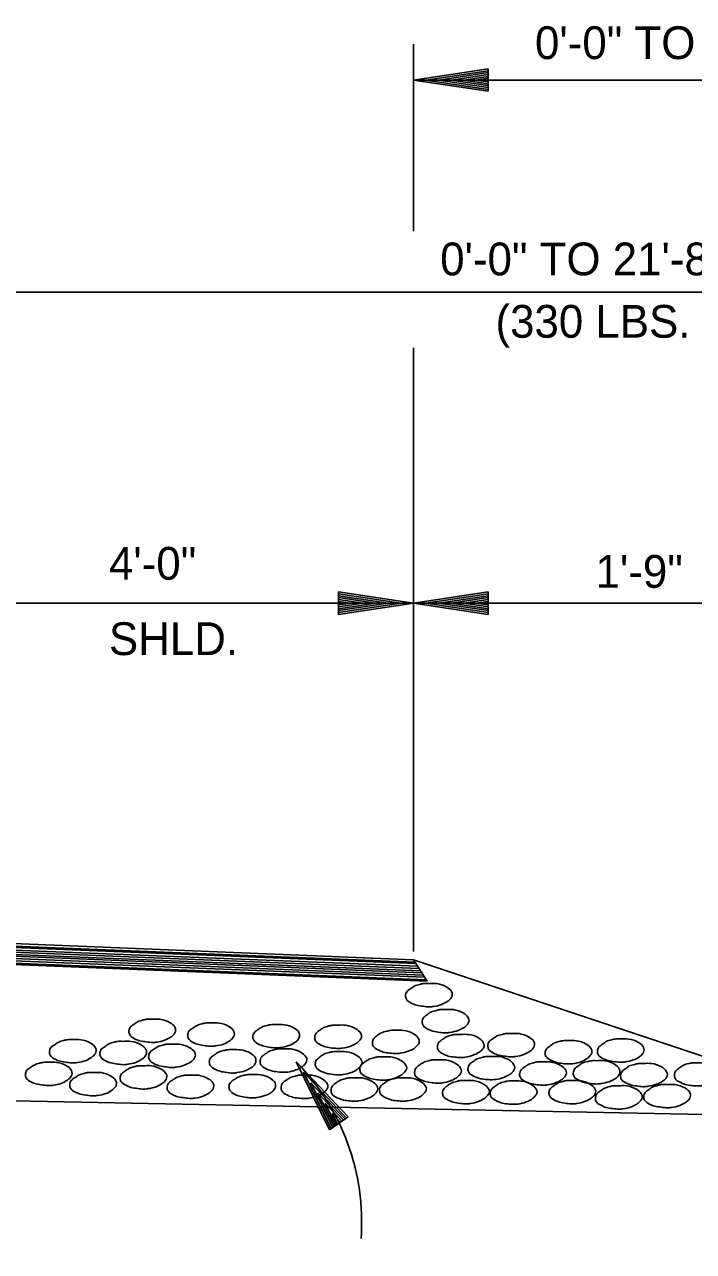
# Model space of a CAD drawing. Extents: x 836 to 5683, y -463 to 1545.
# Drawn here: x 4647.3 to 4769.7, y -331.6 to -107 of the extents above; entities that cross this region are included whole.
import ezdxf

# ---------------------------------------------------------------- set-up
doc = ezdxf.new("R2010")
doc.units = 0
doc.layers.add('Default', color=7, linetype='Continuous')

msp = doc.modelspace()

# ---------------------------------------------------------------- linework, layer by layer
at = {"layer": 'Default'}
for p, q in [((4718.46, -110.62), (4718.46, -144.83)), ((4732.16, -115.15), (4718.46, -117.19)), ((4732.16, -115.48), (4720.73, -117.19)), ((4732.16, -115.83), (4723.1, -117.19)), ((4732.16, -116.16), (4725.38, -117.19)), ((4732.16, -116.55), (4727.7, -117.19)), ((4732.16, -115.15), (4732.16, -119.25)), ((4732.16, -119.25), (4718.46, -117.19)), ((4953.92, -117.19), (4718.46, -117.19)), ((4732.16, -118.9), (4720.73, -117.19)), ((4732.16, -118.56), (4723.1, -117.19)), ((4732.16, -118.2), (4725.38, -117.19)), ((4732.16, -117.87), (4727.7, -117.19)), ((4732.16, -116.86), (4729.97, -117.19)), ((4732.16, -117.52), (4729.97, -117.19)), ((4954.76, -155.99), (4633.46, -155.99)), ((4718.46, -166.17), (4718.46, -189.97)), ((4718.46, -189.97), (4718.46, -276.66)), ((4704.78, -210.88), (4718.46, -212.92)), ((4704.78, -210.88), (4704.78, -214.98)), ((4732.16, -210.88), (4718.46, -212.92)), ((4732.16, -214.98), (4732.16, -210.88)), ((4629.11, -212.92), (4718.46, -212.92)), ((4704.78, -211.21), (4716.17, -212.92)), ((4704.78, -211.57), (4713.83, -212.92)), ((4704.78, -211.9), (4711.56, -212.92)), ((4704.78, -212.27), (4709.2, -212.92)), ((4704.78, -212.6), (4706.93, -212.92)), ((4704.78, -214.98), (4718.46, -212.92)), ((4704.78, -213.61), (4709.2, -212.92)), ((4704.78, -214.3), (4713.83, -212.92)), ((4704.78, -214.64), (4716.17, -212.92)), ((4704.78, -213.94), (4711.56, -212.92)), ((4704.78, -213.25), (4706.93, -212.92)), ((4718.46, -212.92), (4805.51, -212.92)), ((4732.16, -214.98), (4718.46, -212.92)), ((4732.16, -211.21), (4720.74, -212.92)), ((4732.16, -214.64), (4720.74, -212.92)), ((4732.16, -211.57), (4723.09, -212.92)), ((4732.16, -214.3), (4723.09, -212.92)), ((4732.16, -211.9), (4725.38, -212.92)), ((4732.16, -213.94), (4725.38, -212.92)), ((4732.16, -212.27), (4727.69, -212.92)), ((4732.16, -213.61), (4727.69, -212.92)), ((4732.16, -212.6), (4729.96, -212.92)), ((4732.16, -213.25), (4729.96, -212.92)), ((4450.52, -267.41), (4718.46, -278.19)), ((4450.81, -267.86), (4718.74, -278.64)), ((4451.02, -268.2), (4718.91, -278.91)), ((4451.3, -268.63), (4719.21, -279.38)), ((4451.57, -269.06), (4719.46, -279.77)), ((4451.81, -269.43), (4719.76, -280.24)), ((4452.05, -269.82), (4719.96, -280.56)), ((4452.3, -270.21), (4720.25, -281.02)), ((4452.57, -270.64), (4720.5, -281.4)), ((4452.82, -271.03), (4720.79, -281.87)), ((4453.03, -271.36), (4720.95, -282.13)), ((4718.46, -278.19), (4915.99, -344.03)), ((4718.46, -278.19), (4720.96, -282.13)), ((4703.13, -309.3), (4697.01, -296.88)), ((4706.51, -306.93), (4697.01, -296.88)), ((4471.56, -300.53), (4805.51, -307.21)), ((4703.41, -309.12), (4698.33, -298.75)), ((4706.23, -307.17), (4698.33, -298.75)), ((4705.94, -307.34), (4699.67, -300.7)), ((4703.71, -308.91), (4699.67, -300.7)), ((4704, -308.71), (4700.96, -302.57)), ((4705.65, -307.56), (4700.96, -302.57)), ((4705.37, -307.74), (4702.3, -304.47)), ((4704.28, -308.49), (4702.3, -304.47)), ((4703.13, -309.3), (4706.51, -306.93)), ((4705.08, -307.95), (4703.6, -306.33)), ((4704.56, -308.32), (4703.6, -306.33))]:
    msp.add_line(p, q, dxfattribs=at)
msp.add_arc((4667.16, -326.19), 41.83, 355.8236, 44.4822, dxfattribs=at)
for points in [[(4721.22, -282.55), (4722.75, -282.56), (4724.57, -283.2), (4725.46, -284.03), (4725.58, -284.57), (4725.12, -285.49), (4724.6, -285.88), (4723.6, -286.4), (4722.14, -286.74), (4721.38, -286.82), (4720.27, -286.71), (4719.01, -286.5), (4718.06, -286.13), (4717.18, -285.4), (4717.03, -284.82), (4717.29, -284), (4717.99, -283.47), (4718.63, -283.05), (4719.65, -282.7), (4720.28, -282.56), (4721.22, -282.55)], [(4724.26, -287.3), (4725.77, -287.32), (4727.58, -287.94), (4728.48, -288.81), (4728.64, -289.31), (4728.16, -290.25), (4727.63, -290.67), (4726.64, -291.12), (4725.16, -291.51), (4724.4, -291.57), (4723.28, -291.49), (4722.05, -291.27), (4721.1, -290.89), (4720.22, -290.18), (4720.07, -289.58), (4720.33, -288.78), (4721.02, -288.2), (4721.66, -287.77), (4722.69, -287.46), (4723.31, -287.32), (4724.26, -287.3)], [(4670.59, -289.07), (4672.12, -289.08), (4673.94, -289.72), (4674.83, -290.55), (4674.95, -291.09), (4674.49, -292.01), (4673.97, -292.4), (4672.97, -292.92), (4671.51, -293.26), (4670.75, -293.34), (4669.64, -293.23), (4668.38, -293.02), (4667.43, -292.65), (4666.55, -291.92), (4666.4, -291.34), (4666.66, -290.52), (4667.36, -289.99), (4668, -289.57), (4669.02, -289.22), (4669.65, -289.08), (4670.59, -289.07)], [(4681.35, -289.77), (4682.88, -289.78), (4684.7, -290.42), (4685.59, -291.25), (4685.71, -291.79), (4685.25, -292.71), (4684.73, -293.1), (4683.73, -293.62), (4682.27, -293.96), (4681.51, -294.04), (4680.4, -293.93), (4679.14, -293.72), (4678.19, -293.35), (4677.31, -292.62), (4677.16, -292.04), (4677.42, -291.22), (4678.12, -290.69), (4678.76, -290.27), (4679.78, -289.92), (4680.41, -289.78), (4681.35, -289.77)], [(4693.27, -290.04), (4694.81, -290.08), (4696.64, -290.69), (4697.53, -291.56), (4697.63, -292.06), (4697.17, -293.01), (4696.65, -293.42), (4695.67, -293.9), (4694.19, -294.26), (4693.43, -294.32), (4692.32, -294.23), (4691.1, -294.01), (4690.14, -293.64), (4689.25, -292.93), (4689.09, -292.33), (4689.36, -291.5), (4690.05, -290.97), (4690.7, -290.53), (4691.7, -290.21), (4692.34, -290.08), (4693.27, -290.04)], [(4704.59, -290.16), (4706.1, -290.18), (4707.92, -290.82), (4708.84, -291.67), (4708.98, -292.17), (4708.48, -293.11), (4707.95, -293.53), (4706.99, -294.01), (4705.48, -294.38), (4704.74, -294.43), (4703.61, -294.35), (4702.39, -294.14), (4701.44, -293.75), (4700.55, -293.04), (4700.41, -292.42), (4700.68, -291.64), (4701.36, -291.08), (4702.02, -290.64), (4703, -290.32), (4703.62, -290.18), (4704.59, -290.16)], [(4715.18, -291.11), (4716.66, -291.13), (4718.5, -291.75), (4719.39, -292.63), (4719.54, -293.14), (4719.04, -294.04), (4718.51, -294.48), (4717.53, -294.93), (4716.04, -295.32), (4715.29, -295.37), (4714.17, -295.29), (4712.95, -295.09), (4712, -294.7), (4711.1, -294), (4710.96, -293.39), (4711.24, -292.59), (4711.91, -292.02), (4712.56, -291.58), (4713.57, -291.29), (4714.18, -291.13), (4715.18, -291.11)], [(4727.06, -291.86), (4728.54, -291.88), (4730.38, -292.47), (4731.25, -293.34), (4731.41, -293.84), (4730.94, -294.79), (4730.4, -295.19), (4729.41, -295.66), (4727.95, -296.04), (4727.17, -296.1), (4726.06, -296.02), (4724.83, -295.82), (4723.88, -295.41), (4722.98, -294.7), (4722.85, -294.13), (4723.12, -293.31), (4723.8, -292.76), (4724.43, -292.33), (4725.46, -291.98), (4726.08, -291.88), (4727.06, -291.86)], [(4736.27, -291.7), (4737.8, -291.71), (4739.62, -292.35), (4740.51, -293.18), (4740.63, -293.72), (4740.17, -294.64), (4739.65, -295.03), (4738.65, -295.55), (4737.19, -295.89), (4736.43, -295.97), (4735.32, -295.86), (4734.06, -295.65), (4733.11, -295.28), (4732.23, -294.55), (4732.08, -293.97), (4732.34, -293.15), (4733.04, -292.62), (4733.68, -292.2), (4734.7, -291.85), (4735.33, -291.71), (4736.27, -291.7)], [(4656.05, -292.82), (4657.58, -292.83), (4659.4, -293.47), (4660.29, -294.3), (4660.41, -294.84), (4659.95, -295.76), (4659.43, -296.15), (4658.43, -296.67), (4656.97, -297.01), (4656.21, -297.09), (4655.1, -296.98), (4653.84, -296.77), (4652.89, -296.4), (4652.01, -295.67), (4651.86, -295.09), (4652.12, -294.27), (4652.82, -293.74), (4653.46, -293.32), (4654.48, -292.97), (4655.11, -292.83), (4656.05, -292.82)], [(4665.28, -293.13), (4666.81, -293.14), (4668.63, -293.78), (4669.52, -294.61), (4669.64, -295.15), (4669.18, -296.07), (4668.66, -296.46), (4667.66, -296.98), (4666.2, -297.32), (4665.44, -297.4), (4664.33, -297.29), (4663.07, -297.08), (4662.12, -296.71), (4661.24, -295.98), (4661.09, -295.4), (4661.35, -294.58), (4662.05, -294.05), (4662.69, -293.63), (4663.71, -293.28), (4664.34, -293.14), (4665.28, -293.13)], [(4674.2, -293.65), (4675.73, -293.66), (4677.55, -294.3), (4678.44, -295.13), (4678.56, -295.67), (4678.1, -296.59), (4677.58, -296.98), (4676.58, -297.5), (4675.12, -297.84), (4674.36, -297.92), (4673.25, -297.81), (4671.99, -297.6), (4671.04, -297.23), (4670.16, -296.5), (4670.01, -295.92), (4670.27, -295.1), (4670.97, -294.57), (4671.61, -294.15), (4672.63, -293.8), (4673.26, -293.66), (4674.2, -293.65)], [(4746.75, -293), (4748.26, -293.01), (4750.08, -293.65), (4751, -294.51), (4751.14, -295.01), (4750.64, -295.94), (4750.12, -296.36), (4749.15, -296.85), (4747.64, -297.22), (4746.9, -297.27), (4745.77, -297.19), (4744.55, -296.97), (4743.6, -296.58), (4742.71, -295.88), (4742.57, -295.26), (4742.84, -294.48), (4743.52, -293.92), (4744.18, -293.48), (4745.16, -293.15), (4745.78, -293.01), (4746.75, -293)], [(4756.33, -292.69), (4757.84, -292.71), (4759.68, -293.33), (4760.55, -294.19), (4760.69, -294.69), (4760.21, -295.64), (4759.7, -296.04), (4758.7, -296.53), (4757.23, -296.9), (4756.47, -296.95), (4755.36, -296.87), (4754.12, -296.65), (4753.15, -296.26), (4752.26, -295.56), (4752.14, -294.98), (4752.42, -294.16), (4753.11, -293.61), (4753.73, -293.18), (4754.74, -292.83), (4755.38, -292.71), (4756.33, -292.69)], [(4685.29, -294.64), (4686.83, -294.69), (4688.65, -295.3), (4689.54, -296.17), (4689.65, -296.67), (4689.18, -297.62), (4688.67, -298.02), (4687.69, -298.51), (4686.21, -298.86), (4685.44, -298.93), (4684.34, -298.83), (4683.12, -298.61), (4682.15, -298.24), (4681.27, -297.54), (4681.11, -296.93), (4681.38, -296.11), (4682.06, -295.58), (4682.72, -295.14), (4683.71, -294.81), (4684.35, -294.69), (4685.29, -294.64)], [(4694.57, -294.52), (4696.09, -294.53), (4697.91, -295.17), (4698.83, -296.03), (4698.97, -296.53), (4698.47, -297.46), (4697.94, -297.88), (4696.97, -298.37), (4695.46, -298.74), (4694.73, -298.79), (4693.59, -298.71), (4692.38, -298.49), (4691.43, -298.1), (4690.54, -297.4), (4690.4, -296.78), (4690.66, -296), (4691.35, -295.44), (4692, -295), (4692.98, -294.67), (4693.61, -294.53), (4694.57, -294.52)], [(4704.67, -295), (4706.18, -295.02), (4708.01, -295.65), (4708.93, -296.51), (4709.07, -297.01), (4708.57, -297.94), (4708.04, -298.37), (4707.07, -298.85), (4705.56, -299.22), (4704.83, -299.27), (4703.69, -299.19), (4702.48, -298.97), (4701.52, -298.58), (4700.64, -297.88), (4700.5, -297.26), (4700.76, -296.48), (4701.45, -295.92), (4702.1, -295.48), (4703.08, -295.16), (4703.71, -295.02), (4704.67, -295)], [(4712.84, -295.97), (4714.35, -295.98), (4716.17, -296.62), (4717.09, -297.48), (4717.23, -297.98), (4716.73, -298.91), (4716.2, -299.33), (4715.24, -299.81), (4713.73, -300.19), (4712.99, -300.24), (4711.86, -300.16), (4710.64, -299.94), (4709.69, -299.55), (4708.8, -298.85), (4708.66, -298.23), (4708.93, -297.45), (4709.61, -296.89), (4710.27, -296.45), (4711.25, -296.12), (4711.87, -295.98), (4712.84, -295.97)], [(4732.65, -295.9), (4734.13, -295.91), (4735.97, -296.54), (4736.84, -297.41), (4737, -297.91), (4736.53, -298.84), (4735.99, -299.25), (4735, -299.73), (4733.54, -300.11), (4732.76, -300.15), (4731.67, -300.09), (4730.42, -299.89), (4729.47, -299.48), (4728.58, -298.78), (4728.44, -298.19), (4728.72, -297.36), (4729.41, -296.8), (4730.02, -296.37), (4731.05, -296.07), (4731.69, -295.91), (4732.65, -295.9)], [(4651.64, -296.97), (4653.17, -296.98), (4654.99, -297.62), (4655.88, -298.45), (4656, -298.99), (4655.54, -299.91), (4655.02, -300.3), (4654.02, -300.82), (4652.56, -301.16), (4651.8, -301.24), (4650.69, -301.13), (4649.43, -300.92), (4648.48, -300.55), (4647.6, -299.82), (4647.45, -299.24), (4647.71, -298.42), (4648.41, -297.89), (4649.05, -297.47), (4650.07, -297.12), (4650.7, -296.98), (4651.64, -296.97)], [(4668.99, -297.6), (4670.52, -297.61), (4672.34, -298.25), (4673.23, -299.08), (4673.35, -299.62), (4672.89, -300.54), (4672.37, -300.93), (4671.37, -301.45), (4669.91, -301.79), (4669.15, -301.87), (4668.04, -301.76), (4666.78, -301.55), (4665.83, -301.18), (4664.95, -300.45), (4664.8, -299.87), (4665.06, -299.05), (4665.76, -298.52), (4666.4, -298.1), (4667.42, -297.75), (4668.05, -297.61), (4668.99, -297.6)], [(4722.85, -296.51), (4724.36, -296.53), (4726.18, -297.17), (4727.1, -298.02), (4727.24, -298.52), (4726.74, -299.46), (4726.21, -299.88), (4725.25, -300.36), (4723.74, -300.74), (4723, -300.78), (4721.87, -300.7), (4720.65, -300.49), (4719.7, -300.1), (4718.81, -299.39), (4718.67, -298.77), (4718.94, -297.99), (4719.62, -297.43), (4720.28, -297), (4721.26, -296.67), (4721.88, -296.53), (4722.85, -296.51)], [(4742.08, -296.89), (4743.59, -296.9), (4745.41, -297.54), (4746.33, -298.4), (4746.47, -298.9), (4745.97, -299.83), (4745.45, -300.25), (4744.48, -300.73), (4742.97, -301.11), (4742.24, -301.16), (4741.1, -301.08), (4739.88, -300.86), (4738.93, -300.47), (4738.04, -299.77), (4737.9, -299.15), (4738.17, -298.37), (4738.85, -297.81), (4739.51, -297.37), (4740.49, -297.04), (4741.11, -296.9), (4742.08, -296.89)], [(4751.91, -296.67), (4753.42, -296.69), (4755.26, -297.31), (4756.14, -298.19), (4756.26, -298.68), (4755.81, -299.6), (4755.28, -300.04), (4754.28, -300.51), (4752.8, -300.87), (4752.07, -300.94), (4750.93, -300.85), (4749.68, -300.65), (4748.76, -300.26), (4747.85, -299.56), (4747.72, -298.96), (4748, -298.14), (4748.67, -297.59), (4749.31, -297.14), (4750.32, -296.83), (4750.96, -296.69), (4751.91, -296.67)], [(4760.58, -297.18), (4762.07, -297.19), (4763.88, -297.82), (4764.79, -298.69), (4764.94, -299.17), (4764.46, -300.11), (4763.91, -300.54), (4762.93, -300.99), (4761.45, -301.35), (4760.7, -301.43), (4759.61, -301.34), (4758.35, -301.13), (4757.41, -300.76), (4756.5, -300.06), (4756.37, -299.45), (4756.65, -298.63), (4757.34, -298.08), (4757.96, -297.64), (4758.97, -297.35), (4759.63, -297.19), (4760.58, -297.18)], [(4770.41, -297.06), (4771.92, -297.07), (4773.76, -297.68), (4774.65, -298.55), (4774.79, -299.04), (4774.3, -300), (4773.77, -300.41), (4772.78, -300.86), (4771.3, -301.23), (4770.56, -301.3), (4769.43, -301.22), (4768.19, -301.01), (4767.26, -300.63), (4766.34, -299.91), (4766.23, -299.33), (4766.5, -298.52), (4767.17, -297.96), (4767.82, -297.52), (4768.82, -297.2), (4769.46, -297.07), (4770.41, -297.06)], [(4659.77, -298.85), (4661.3, -298.86), (4663.12, -299.5), (4664.01, -300.33), (4664.13, -300.87), (4663.67, -301.79), (4663.15, -302.18), (4662.15, -302.7), (4660.69, -303.04), (4659.93, -303.12), (4658.82, -303.01), (4657.56, -302.8), (4656.61, -302.43), (4655.73, -301.7), (4655.58, -301.12), (4655.84, -300.3), (4656.54, -299.77), (4657.18, -299.35), (4658.2, -299), (4658.83, -298.86), (4659.77, -298.85)], [(4677.58, -299.32), (4679.11, -299.33), (4680.93, -299.97), (4681.82, -300.8), (4681.94, -301.34), (4681.48, -302.26), (4680.96, -302.65), (4679.96, -303.17), (4678.5, -303.51), (4677.74, -303.59), (4676.63, -303.48), (4675.37, -303.27), (4674.42, -302.9), (4673.54, -302.17), (4673.39, -301.59), (4673.65, -300.77), (4674.35, -300.24), (4674.99, -299.82), (4676.01, -299.47), (4676.64, -299.33), (4677.58, -299.32)], [(4688.89, -299.21), (4690.43, -299.25), (4692.25, -299.86), (4693.14, -300.73), (4693.25, -301.23), (4692.78, -302.18), (4692.27, -302.59), (4691.29, -303.07), (4689.81, -303.43), (4689.04, -303.49), (4687.94, -303.4), (4686.72, -303.18), (4685.75, -302.81), (4684.87, -302.11), (4684.71, -301.5), (4684.98, -300.67), (4685.66, -300.14), (4686.32, -299.71), (4687.31, -299.38), (4687.95, -299.25), (4688.89, -299.21)], [(4698.42, -299.33), (4699.94, -299.35), (4701.76, -299.99), (4702.68, -300.84), (4702.82, -301.34), (4702.32, -302.28), (4701.79, -302.7), (4700.82, -303.18), (4699.31, -303.55), (4698.58, -303.6), (4697.44, -303.52), (4696.23, -303.31), (4695.28, -302.92), (4694.39, -302.21), (4694.25, -301.59), (4694.51, -300.81), (4695.2, -300.25), (4695.85, -299.81), (4696.83, -299.49), (4697.46, -299.35), (4698.42, -299.33)], [(4707.56, -299.81), (4709.07, -299.83), (4710.89, -300.47), (4711.81, -301.33), (4711.95, -301.83), (4711.45, -302.76), (4710.92, -303.18), (4709.95, -303.66), (4708.44, -304.04), (4707.71, -304.08), (4706.57, -304.01), (4705.36, -303.79), (4704.41, -303.4), (4703.52, -302.7), (4703.38, -302.07), (4703.64, -301.3), (4704.33, -300.73), (4704.98, -300.3), (4705.97, -299.97), (4706.59, -299.83), (4707.56, -299.81)], [(4716.44, -299.81), (4717.95, -299.83), (4719.77, -300.47), (4720.69, -301.33), (4720.83, -301.83), (4720.33, -302.76), (4719.8, -303.18), (4718.84, -303.66), (4717.33, -304.04), (4716.59, -304.08), (4715.46, -304.01), (4714.24, -303.79), (4713.29, -303.4), (4712.4, -302.7), (4712.26, -302.07), (4712.53, -301.3), (4713.21, -300.73), (4713.87, -300.3), (4714.85, -299.97), (4715.47, -299.83), (4716.44, -299.81)], [(4727.97, -300.3), (4729.48, -300.31), (4731.3, -300.95), (4732.22, -301.81), (4732.36, -302.31), (4731.86, -303.24), (4731.33, -303.66), (4730.37, -304.15), (4728.86, -304.52), (4728.12, -304.57), (4726.99, -304.49), (4725.77, -304.27), (4724.82, -303.88), (4723.93, -303.18), (4723.79, -302.56), (4724.06, -301.78), (4724.74, -301.22), (4725.4, -300.78), (4726.38, -300.45), (4727, -300.31), (4727.97, -300.3)], [(4736.69, -300.38), (4738.2, -300.4), (4740.02, -301.04), (4740.94, -301.9), (4741.08, -302.4), (4740.58, -303.33), (4740.05, -303.75), (4739.09, -304.23), (4737.57, -304.61), (4736.84, -304.65), (4735.7, -304.58), (4734.49, -304.36), (4733.54, -303.97), (4732.65, -303.27), (4732.51, -302.64), (4732.78, -301.87), (4733.46, -301.3), (4734.12, -300.87), (4735.1, -300.54), (4735.72, -300.4), (4736.69, -300.38)], [(4747.43, -300.3), (4748.94, -300.31), (4750.77, -300.95), (4751.69, -301.81), (4751.83, -302.31), (4751.33, -303.24), (4750.8, -303.66), (4749.83, -304.15), (4748.32, -304.52), (4747.59, -304.57), (4746.45, -304.49), (4745.23, -304.27), (4744.28, -303.88), (4743.4, -303.18), (4743.26, -302.56), (4743.52, -301.78), (4744.21, -301.22), (4744.86, -300.78), (4745.84, -300.45), (4746.47, -300.31), (4747.43, -300.3)], [(4755.95, -301.26), (4757.46, -301.27), (4759.29, -301.91), (4760.2, -302.77), (4760.34, -303.27), (4759.85, -304.2), (4759.32, -304.62), (4758.35, -305.11), (4756.84, -305.48), (4756.11, -305.53), (4754.97, -305.45), (4753.75, -305.23), (4752.8, -304.84), (4751.91, -304.14), (4751.77, -303.52), (4752.04, -302.74), (4752.72, -302.18), (4753.38, -301.74), (4754.36, -301.41), (4754.98, -301.27), (4755.95, -301.26)], [(4764.82, -301.02), (4766.33, -301.04), (4768.14, -301.66), (4769.06, -302.54), (4769.17, -303.02), (4768.71, -303.97), (4768.18, -304.37), (4767.2, -304.86), (4765.71, -305.23), (4764.96, -305.29), (4763.84, -305.18), (4762.61, -304.98), (4761.64, -304.61), (4760.77, -303.88), (4760.61, -303.3), (4760.88, -302.49), (4761.58, -301.93), (4762.22, -301.51), (4763.24, -301.18), (4763.85, -301.04), (4764.82, -301.02)]]:
    msp.add_spline(points, degree=3, dxfattribs=at)

# ---------------------------------------------------------------- texts
for s, p in [('0\'-0" TO 25\'-5" ACHM SURFACE COURSE (1/2")', (4740.71, -113.35)), ('0\'-0" TO 21\'-8" ACHM BINDER COURSE (1")', (4723.36, -152.93)), ('(330 LBS. PER SQ. YD.) & TACK COAT', (4733.48, -164.35)), ('4\'-0"', (4662.75, -208.64)), ('1\'-9"', (4751.79, -210.12)), ('SHLD.', (4662.75, -222.43))]:
    msp.add_text(s, height=6, dxfattribs=at).set_placement(p)

doc.saveas('drawing.dxf')
